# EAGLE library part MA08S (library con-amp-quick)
AMP QUICK CONNECTOR
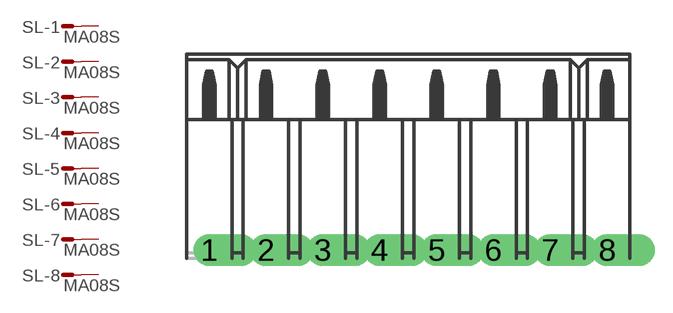
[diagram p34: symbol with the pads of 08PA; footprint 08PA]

Designator prefix SL; gates -1=M -2=M -3=M -4=M -5=M -6=M -7=M -8=M

## MA08S  [08PA]
1  -1:S  pas
2  -2:S  pas
3  -3:S  pas
4  -4:S  pas
5  -5:S  pas
6  -6:S  pas
7  -7:S  pas
8  -8:S  pas

## Footprint 08PA (pad centres in mm)
AMP QUICK CONNECTOR
drill 0.914 offset: 1 -8.89,0; 2 -6.35,0; 3 -3.81,0; 4 -1.27,0; 5 1.27,0; 6 3.81,0; 7 6.35,0; 8 8.89,0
